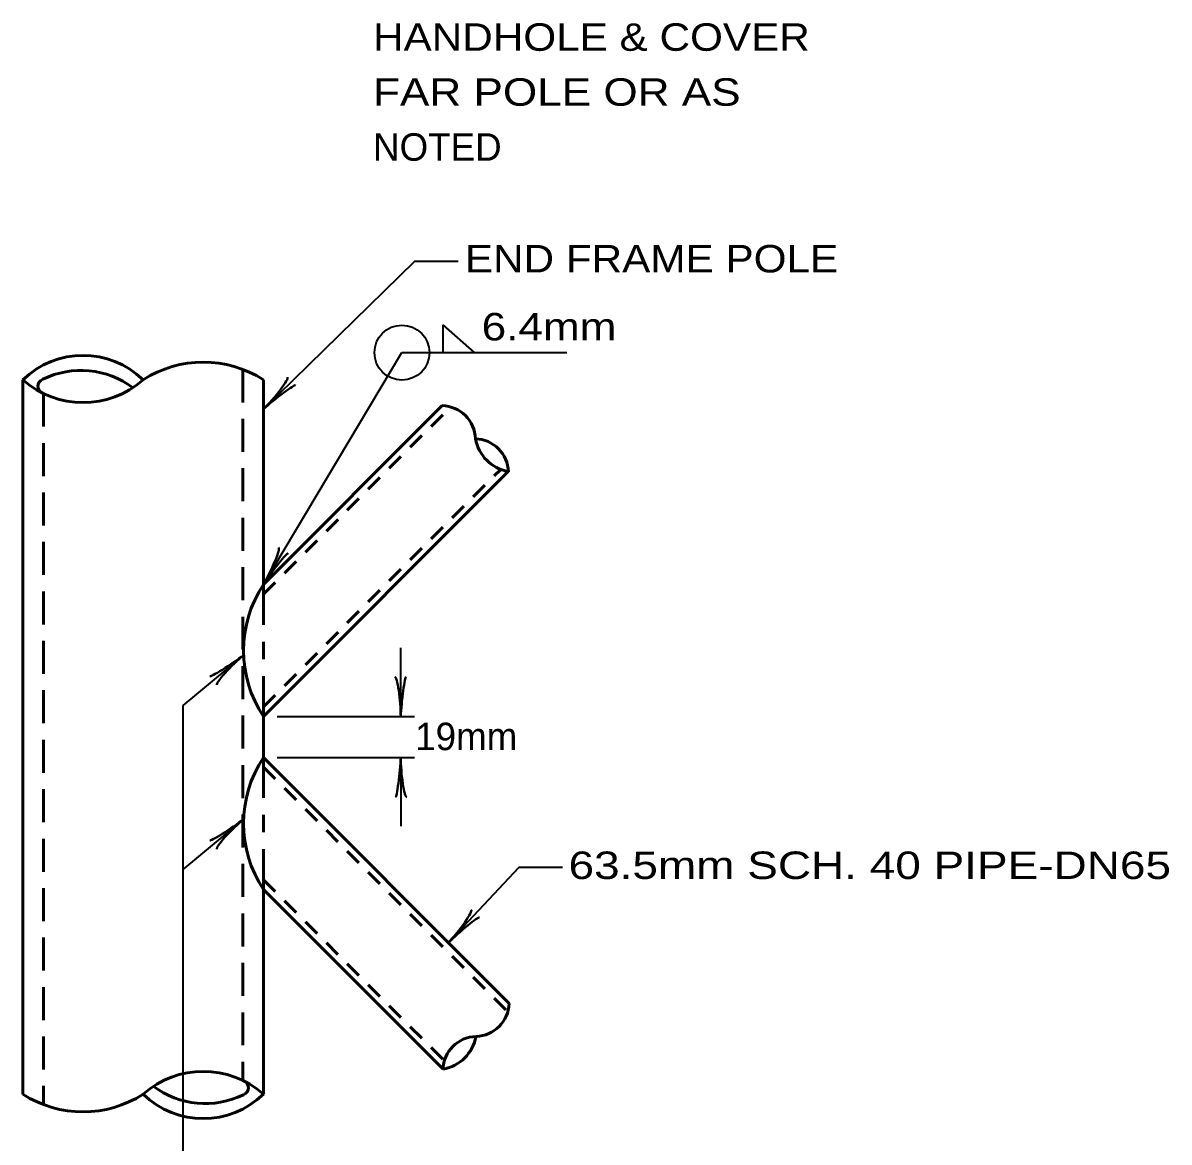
# Model space of a CAD drawing. Extents: x -35 to 821, y -13 to 531.
# Drawn here: x 169.4 to 269.5, y 247.3 to 345.1 of the extents above; entities that cross this region are included whole.
import ezdxf

# ---------------------------------------------------------------- set-up
doc = ezdxf.new("R2010")
doc.units = 0
doc.header["$LTSCALE"] = 0.96
doc.linetypes.add('MEDIUM_DASHED', pattern=[4.5, 3, -1.5])
doc.linetypes.add('SHORT_DASHED', pattern=[2.7, 1.5, -1.2])
doc.layers.add('1', color=7, linetype='Continuous', lineweight=53)

msp = doc.modelspace()

# ---------------------------------------------------------------- linework, layer by layer
at = {"layer": '1', "lineweight": 35}
for p, q in [((190.3974, 296.0145), (202.4973, 316.2653)), ((202.4973, 316.2653), (216.8973, 316.2653)), ((202.3974, 284.4941), (202.3974, 290.4941)), ((188.6736, 289.8443), (183.3567, 285.4461)), ((191.5974, 284.4941), (203.5974, 284.4941)), ((191.5974, 280.8941), (203.5974, 280.8941)), ((202.3974, 280.8941), (202.3974, 274.8941)), ((188.6723, 275.5087), (183.3567, 271.1116))]:
    msp.add_line(p, q, dxfattribs=at)
at = {"layer": '1', "linetype": 'MEDIUM_DASHED'}
for p, q in [((188.5974, 314.8031), (188.5974, 252.6974)), ((171.1974, 312.6908), (171.1974, 250.5851))]:
    msp.add_line(p, q, dxfattribs=at)
at = {"layer": '1'}
for p, q in [((169.3974, 313.8941), (169.3974, 251.4941)), ((190.3974, 313.8941), (190.3974, 296.0145)), ((190.3974, 296.0145), (206.0194, 311.6365)), ((190.3974, 284.4941), (211.7796, 305.8763)), ((190.3974, 296.0145), (190.3974, 292.5043)), ((190.3974, 291.0043), (190.3974, 289.5043)), ((190.3974, 288.0043), (190.3974, 284.4941)), ((190.3974, 280.8941), (211.8612, 259.4299)), ((190.3974, 280.8941), (190.3974, 277.3839)), ((190.3974, 275.8839), (190.3974, 274.3839)), ((190.3974, 272.8839), (190.3974, 269.3737)), ((190.3974, 269.3734), (206.1009, 253.6696)), ((190.3974, 269.3734), (190.3974, 251.4941))]:
    msp.add_line(p, q, dxfattribs=at)
at = {"layer": '1', "linetype": 'SHORT_DASHED'}
for p, q in [((190.3974, 295.166), (206.7542, 311.5228)), ((190.3974, 285.3426), (211.1215, 306.0667)), ((190.3974, 280.0455), (211.7475, 258.695)), ((190.3974, 270.2218), (206.2017, 254.4172))]:
    msp.add_line(p, q, dxfattribs=at)
at = {"layer": '1', "lineweight": 35}
for points in [[(190.3974, 311.3292), (203.6232, 324.2516), (207.4104, 324.2516)], [(206.0973, 316.2653), (206.0973, 318.6653), (208.7973, 316.2653)], [(183.3567, 285.4461), (183.3567, 243.8761), (196.8044, 243.8761)], [(206.5606, 264.7306), (212.7329, 271.3164), (216.5201, 271.3164)]]:
    msp.add_lwpolyline(points, dxfattribs=at)
at = {"layer": '1'}
msp.add_lwpolyline([(190.3974, 284.4941), (190.3974, 282.6941), (190.3974, 280.8941)], dxfattribs=at)
at = {"layer": '1', "lineweight": 35}
msp.add_circle((202.4973, 316.2653), 2.4, dxfattribs=at)
at = {"layer": '1'}
for centre, radius, start, end in [((174.6474, 308.5), 7.5272, 45.77548, 134.22453), ((185.1474, 305.735), 9.7022, 57.24064, 122.75936), ((174.4566, 307.0767), 7.6317, 53.28342, 115.75809), ((174.6474, 319.7993), 7.9015, 228.36161, 311.63839), ((171.371, 313.3297), 0.662, 110.41349, 254.79699), ((205.9352, 308.6604), 2.9773, 1.62229, 88.3797), ((208.8271, 305.7686), 2.9773, 1.62229, 88.3797), ((212.4455, 309.4104), 3.5963, 190.66794, 259.33007), ((199.1108, 290.2543), 10.4452, 146.53236, 213.46763), ((199.1108, 275.1339), 10.4452, 146.53237, 213.46764), ((208.8851, 259.5141), 2.9773, 271.62229, 358.3797), ((209.0535, 253.562), 2.9773, 91.6203, 178.37771), ((205.4351, 257.2038), 3.5963, 280.66993, 349.33206), ((185.1474, 245.5889), 7.9015, 48.36161, 131.63839), ((188.4238, 252.0585), 0.662, 290.41349, 74.79699), ((174.6474, 259.6532), 9.7022, 237.24064, 302.75936), ((185.1474, 256.8882), 7.5272, 225.77548, 314.22453), ((185.3382, 258.3115), 7.6317, 233.28342, 295.75809)]:
    msp.add_arc(centre, radius, start, end, dxfattribs=at)
at = {"layer": '1', "lineweight": 40}
for centre, major_axis, ratio, start_param, end_param in [((191.1023, 312.4815), (-1.4017, -1.6316), 0.122415, 0.89635335, 3.14159265), ((191.1023, 312.4815), (-1.4017, -1.6316), 0.122415, 0.89635335, 3.14159265), ((191.5366, 312.0873), (1.6549, 1.3222), 0.07063, 6.28230741, 8.55970261), ((191.5366, 312.0873), (1.6549, 1.3222), 0.07063, 6.28230741, 8.55970261), ((190.7844, 297.3086), (-0.9382, -1.9356), 0.122415, 0.89635335, 3.14159265), ((191.305, 297.0385), (1.262, 1.7012), 0.07063, 6.28230741, 8.55970261), ((187.4757, 289.1829), (-1.7584, -1.1811), 0.07063, 6.28230741, 8.55970261), ((187.4757, 289.1829), (-1.7584, -1.1811), 0.07063, 6.28230741, 8.55970261), ((187.876, 288.7542), (1.5317, 1.5102), 0.122415, 0.89635335, 3.14159265), ((187.876, 288.7542), (1.5317, 1.5102), 0.122415, 0.89635335, 3.14159265), ((202.0658, 285.8035), (0.1874, -2.1428), 0.122415, 0.89635335, 3.14159265), ((202.0658, 285.8035), (0.1874, -2.1428), 0.122415, 0.89635335, 3.14159265), ((202.6513, 285.8387), (-0.2108, -2.1077), 0.07063, 3.14071475, 5.41810995), ((202.6513, 285.8387), (-0.2108, -2.1077), 0.07063, 3.14071475, 5.41810995), ((202.1435, 279.5495), (0.2108, 2.1077), 0.07063, 3.14071475, 5.41810995), ((202.1435, 279.5495), (0.2108, 2.1077), 0.07063, 3.14071475, 5.41810995), ((202.729, 279.5847), (-0.1874, 2.1428), 0.122415, 0.89635335, 3.14159265), ((202.729, 279.5847), (-0.1874, 2.1428), 0.122415, 0.89635335, 3.14159265), ((187.4744, 274.8473), (1.7584, 1.181), 0.07063, 3.14071475, 5.41810995), ((187.4744, 274.8473), (1.7584, 1.181), 0.07063, 3.14071475, 5.41810995), ((187.8747, 274.4186), (1.5317, 1.5102), 0.122415, 0.89635335, 3.14159265), ((187.8747, 274.4186), (1.5317, 1.5102), 0.122415, 0.89635335, 3.14159265), ((207.2141, 265.9128), (-1.3286, -1.6916), 0.122415, 0.89635335, 3.14159265), ((207.2141, 265.9128), (-1.3286, -1.6916), 0.122415, 0.89635335, 3.14159265), ((207.6653, 265.538), (1.5951, 1.3938), 0.07063, 6.28230741, 8.55970261), ((207.6653, 265.538), (1.5951, 1.3938), 0.07063, 6.28230741, 8.55970261)]:
    msp.add_ellipse(centre, major_axis=major_axis, ratio=ratio, start_param=start_param, end_param=end_param, dxfattribs=at)

# ---------------------------------------------------------------- texts
at = {"layer": '1'}
for s, width, p in [('HANDHOLE & COVER', 1.15, (199.9743, 342.63)), ('FAR POLE OR AS', 1.2, (199.9743, 337.83)), ('END FRAME POLE', 1.15, (207.9921, 323.2715)), ('6.4mm', 1.2, (209.461, 317.3327)), ('63.5mm SCH. 40 PIPE-DN65', 1.25, (217.0469, 270.2899))]:
    msp.add_text(s, height=2.4, dxfattribs=dict(at, width=width)).set_placement(p)
for s, p in [('NOTED', (199.9743, 333.03)), ('19mm', (203.6558, 281.5447))]:
    msp.add_text(s, height=2.4, dxfattribs=at).set_placement(p)

doc.saveas('drawing.dxf')
